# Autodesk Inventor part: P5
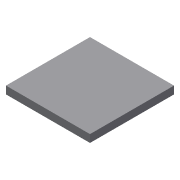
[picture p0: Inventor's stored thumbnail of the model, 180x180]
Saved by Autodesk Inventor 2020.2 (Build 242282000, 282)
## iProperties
Created: 2005-11
Part Number: P5
Document SubType Name: Modeling
Designer: F.Stasiak
Density: 1 g/cm^3
Material: Ogólny
Appearance: Domyślna
Manager: www.cadconsulting.pl
Company: Fabian Stasiak CAD Consulting
Author: F.Stasiak
Subject: Zbiór ćwiczeń. Autodesk Inventor 2020. Kurs podstawowy
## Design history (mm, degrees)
sketch "Szkic1"
  geometry: L1 (55, 55)-(55, -55); L2 (55, -55)-(-55, -55); L3 (-55, -55)-(-55, 55); L4 (-55, 55)-(55, 55); 2 further points
  constraints: 8 end point, 1 coincident, 7 other
  dimensions: "d0" = 110 distance of L1.end L2.end
extrude "Wyciągnięcie proste1" new body sketch "Szkic1" distance "d1" = 10; taper "d2" = 0 deg
node "Bryła1"
node "Korpusy bryłowe"
node "Korpusy powierzchniowe"
